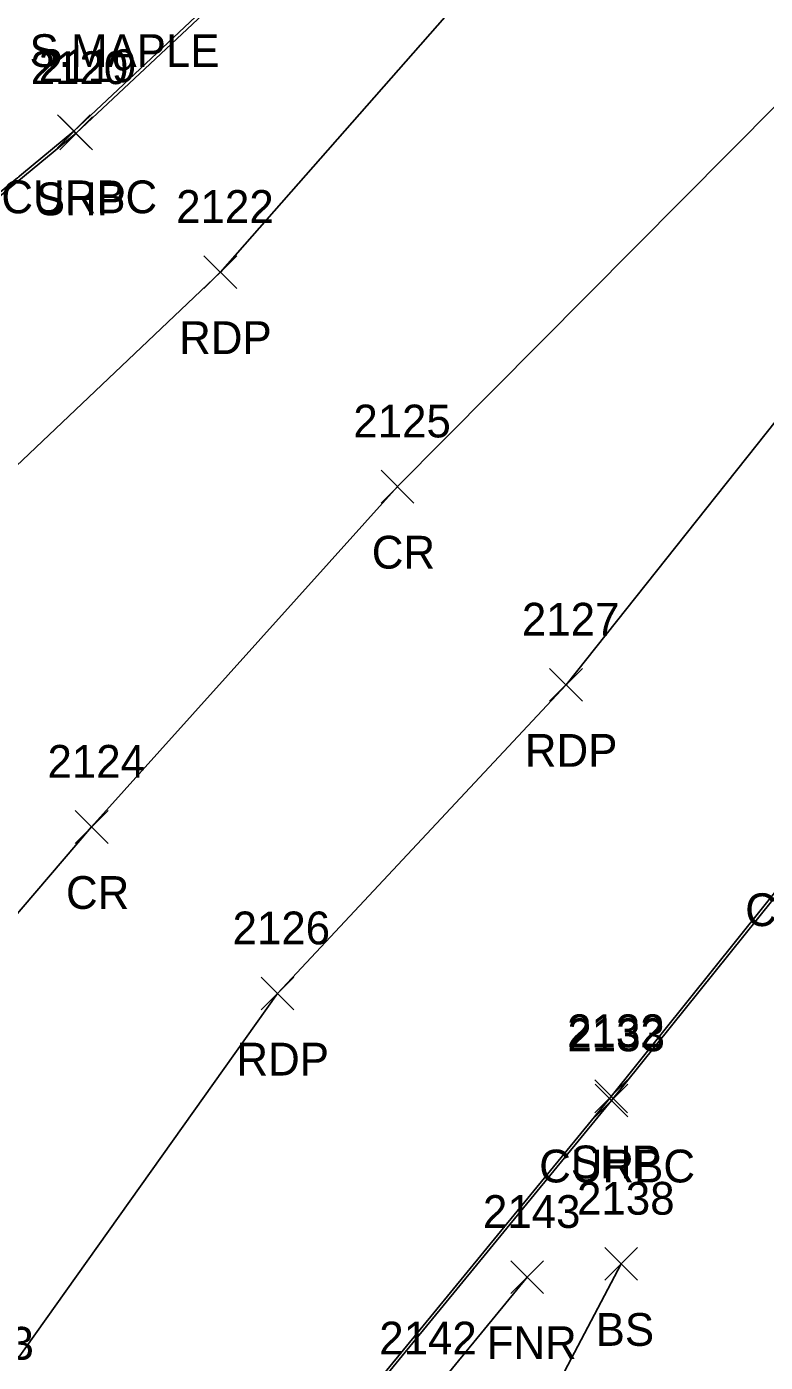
# Model space of a CAD drawing. Extents: x 1462668 to 1465147, y 550359 to 557351.
# Drawn here: x 1464792.3 to 1464837.4, y 552746.4 to 552827.8 of the extents above; entities that cross this region are included whole.
import ezdxf

# ---------------------------------------------------------------- set-up
doc = ezdxf.new("R2010")
doc.units = 0
for name, color, linetype in [('L_A', 7, 'Continuous'), ('L_C', 7, 'Continuous'), ('L_I', 7, 'Continuous'), ('L_TIC', 7, 'Continuous'), ('LELB', 7, 'Continuous'), ('LFNC', 7, 'Continuous'), ('P_A', 7, 'Continuous'), ('P_I', 7, 'Continuous'), ('P_TIC', 7, 'Continuous'), ('PET', 7, 'Continuous'), ('PRC', 7, 'Continuous'), ('PSP', 7, 'Continuous'), ('R_A', 7, 'Continuous'), ('R_I', 7, 'Continuous'), ('R_TIC', 7, 'Continuous'), ('RC', 7, 'Continuous')]:
    doc.layers.add(name, color=color, linetype=linetype)

msp = doc.modelspace()

# ---------------------------------------------------------------- linework, layer by layer
at = {"layer": 'L_TIC'}
for points in [[(1464827.563, 552751.392), (1464829.563, 552753.392)], [(1464829.563, 552751.392), (1464827.563, 552753.392)], [(1464821.82, 552750.584), (1464823.82, 552752.584)], [(1464823.82, 552750.584), (1464821.82, 552752.584)]]:
    msp.add_lwpolyline(points, dxfattribs=at)
at = {"layer": 'LELB'}
msp.add_lwpolyline([(1464828.563, 552752.392), (1464819.989, 552736.126), (1464831.31, 552732.245), (1464867.473, 552723.664), (1464878.187, 552720.928), (1464883.47, 552728.792), (1464898.847, 552749.229), (1464914.904, 552763.866)], dxfattribs=at)
at = {"layer": 'LFNC'}
msp.add_lwpolyline([(1464811.414, 552738.233), (1464816.492, 552743.867), (1464822.82, 552751.584)], dxfattribs=at)
at = {"layer": 'P_TIC'}
for points in [[(1464794.307, 552820.347), (1464796.307, 552822.347)], [(1464796.307, 552820.347), (1464794.307, 552822.347)], [(1464803.102, 552811.882), (1464805.102, 552813.882)], [(1464805.102, 552811.882), (1464803.102, 552813.882)], [(1464813.91, 552798.797), (1464815.91, 552800.797)], [(1464815.91, 552798.797), (1464813.91, 552800.797)], [(1464824.197, 552786.709), (1464826.197, 552788.709)], [(1464826.197, 552786.709), (1464824.197, 552788.709)], [(1464795.248, 552778.041), (1464797.248, 552780.041)], [(1464797.248, 552778.041), (1464795.248, 552780.041)], [(1464806.596, 552767.88), (1464808.596, 552769.88)], [(1464808.596, 552767.88), (1464806.596, 552769.88)], [(1464826.956, 552761.607), (1464828.956, 552763.607)], [(1464828.956, 552761.607), (1464826.956, 552763.607)]]:
    msp.add_lwpolyline(points, dxfattribs=at)
at = {"layer": 'PET'}
for points in [[(1464690.947, 552665.59), (1464705.966, 552689.946), (1464730.955, 552728.42), (1464756.781, 552757.934), (1464781.557, 552791.493), (1464804.102, 552812.882), (1464834.316, 552847.222), (1464855.038, 552863.895), (1464867.103, 552873.049), (1464879.297, 552886.587)], [(1464703.972, 552639.46), (1464728.768, 552667.058), (1464755.897, 552707.968), (1464789.544, 552743.549), (1464807.596, 552768.88), (1464825.197, 552787.709), (1464842.925, 552809.981), (1464865.689, 552832.752), (1464880.577, 552846.679), (1464904.1, 552869.155)]]:
    msp.add_lwpolyline(points, dxfattribs=at)
at = {"layer": 'PRC'}
msp.add_lwpolyline([(1464698.348, 552651.154), (1464716.319, 552677.602), (1464744.518, 552715.543), (1464772.099, 552750.166), (1464779.182, 552759.107), (1464796.248, 552779.041), (1464814.91, 552799.797), (1464849.704, 552834.84), (1464867.527, 552848.824), (1464892.143, 552871.144)], dxfattribs=at)
at = {"layer": 'PSP'}
for points in [[(1464713.42, 552621.664), (1464703.882, 552639.321), (1464698.154, 552650.89), (1464690.708, 552665.219), (1464681.101, 552683.158), (1464703.999, 552722.049), (1464716.476, 552737.914), (1464734.78, 552760.749), (1464735.815, 552761.915), (1464745.244, 552772.268), (1464746.275, 552773.345), (1464761.553, 552790.01), (1464762.974, 552792.101), (1464763.764, 552794.246), (1464784.888, 552812.77), (1464795.307, 552821.347), (1464823.73, 552847.994), (1464827.491, 552852.408)], [(1464713.638, 552621.474), (1464720.301, 552630.087), (1464743.111, 552657.957), (1464771.732, 552693.186), (1464802.941, 552732.092), (1464806.696, 552736.716), (1464807.512, 552737.686), (1464827.956, 552762.607), (1464840.309, 552778.015), (1464860.303, 552803.036), (1464847.059, 552806.202), (1464846.959, 552807.406), (1464865.094, 552816.001), (1464884.928, 552820.043), (1464894.44, 552821.201), (1464905.203, 552819.488), (1464914.433, 552816.323), (1464923.048, 552811.383)]]:
    msp.add_lwpolyline(points, dxfattribs=at)
at = {"layer": 'R_TIC'}
for points in [[(1464794.156, 552820.468), (1464796.156, 552822.468)], [(1464796.156, 552820.468), (1464794.156, 552822.468)], [(1464826.977, 552761.359), (1464828.977, 552763.359)], [(1464828.977, 552761.359), (1464826.977, 552763.359)]]:
    msp.add_lwpolyline(points, dxfattribs=at)
at = {"layer": 'RC'}
for points in [[(1464771.802, 552815.701), (1464775.868, 552813.45), (1464781.504, 552812.417), (1464784.857, 552812.949), (1464795.156, 552821.468), (1464823.516, 552848.121), (1464827.256, 552852.644), (1464829.76, 552857.171), (1464830.463, 552862.196)], [(1464714.099, 552621.115), (1464713.719, 552621.379), (1464720.509, 552629.873), (1464743.204, 552657.681), (1464745.714, 552660.868), (1464771.872, 552693.086), (1464801.879, 552730.35), (1464803.144, 552731.976), (1464806.816, 552736.568), (1464807.62, 552737.531), (1464827.977, 552762.359), (1464840.547, 552777.993), (1464860.732, 552803.16), (1464848.013, 552806.274), (1464847.397, 552807.425), (1464865.211, 552815.863), (1464884.883, 552819.617), (1464894.442, 552820.827), (1464904.964, 552819.101), (1464914.17, 552815.928), (1464922.75, 552811.237)]]:
    msp.add_lwpolyline(points, dxfattribs=at)

# ---------------------------------------------------------------- texts
at = {"layer": 'L_A'}
for s, p in [('BS', (1464827.004, 552747.392)), ('FNR', (1464820.355, 552746.584))]:
    msp.add_text(s, height=2, dxfattribs=at).set_placement(p)
at = {"layer": 'L_C'}
msp.add_text('S.MAPLE', height=2, dxfattribs=at).set_placement((1464792.458, 552825.387))
at = {"layer": 'L_I'}
for s, p in [('2138', (1464825.87, 552755.392)), ('2143', (1464820.127, 552754.584)), ('2142', (1464813.799, 552746.867))]:
    msp.add_text(s, height=2, dxfattribs=at).set_placement(p)
at = {"layer": 'P_A'}
for s, p in [('SHP', (1464792.843, 552816.347)), ('RDP', (1464801.59, 552807.882)), ('CR', (1464813.343, 552794.797)), ('RDP', (1464822.685, 552782.709)), ('CR', (1464794.681, 552774.041)), ('RDP', (1464805.085, 552763.88)), ('SHP', (1464825.491, 552757.607))]:
    msp.add_text(s, height=2, dxfattribs=at).set_placement(p)
at = {"layer": 'P_I'}
for s, p in [('2120', (1464792.528, 552824.347)), ('2122', (1464801.409, 552815.882)), ('2125', (1464812.217, 552802.797)), ('2127', (1464822.504, 552790.709)), ('2124', (1464793.555, 552782.041)), ('2126', (1464804.848, 552771.88)), ('2132', (1464825.263, 552765.607)), ('1903', (1464786.773, 552746.549))]:
    msp.add_text(s, height=2, dxfattribs=at).set_placement(p)
at = {"layer": 'R_A'}
for p in [(1464790.738, 552816.468), (1464836.13, 552772.993), (1464823.559, 552757.359)]:
    msp.add_text('CURBC', height=2, dxfattribs=at).set_placement(p)
at = {"layer": 'R_I'}
for s, p in [('2119', (1464793.022, 552824.468)), ('2133', (1464825.284, 552765.359))]:
    msp.add_text(s, height=2, dxfattribs=at).set_placement(p)

doc.saveas('drawing.dxf')
